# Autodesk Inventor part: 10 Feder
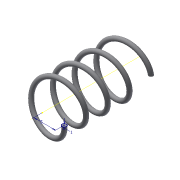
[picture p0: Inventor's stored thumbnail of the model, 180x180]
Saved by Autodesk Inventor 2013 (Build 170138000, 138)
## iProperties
Created: 2012-10
Part Number: 10 Feder
Material: Allgemein
Vendor: www.inventor-faq.de
Document SubType Name: Modeling
Designer: Administrator
Manufacturer: www.inventor-faq.de
Density: 1 g/cm^3
RuleStatus: InUse
AfterDocOpen0: inventorfaq
BeforeDocSave0: inventorfaq
Author: Administrator
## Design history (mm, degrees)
sketch "Skizze1"
  geometry: C1 r 0.5 at (5, 0); 1 further point
  constraints: 1 centre point, 1 horizontal alignment
  dimensions: "d0" = 1 diameter of C1; "d1" = 5 distance of C1.centre point (0, 0)
feature "Spirale1" sketch "Skizze1" pitch "d2" = 5; turns "d4" = 4; dims "d3" = 10, "d5" = 0, angle "d6" = 90 deg, angle "d7" = 90 deg, "d8" = 0, "d9" = 0
node "Volumenkörper1"
